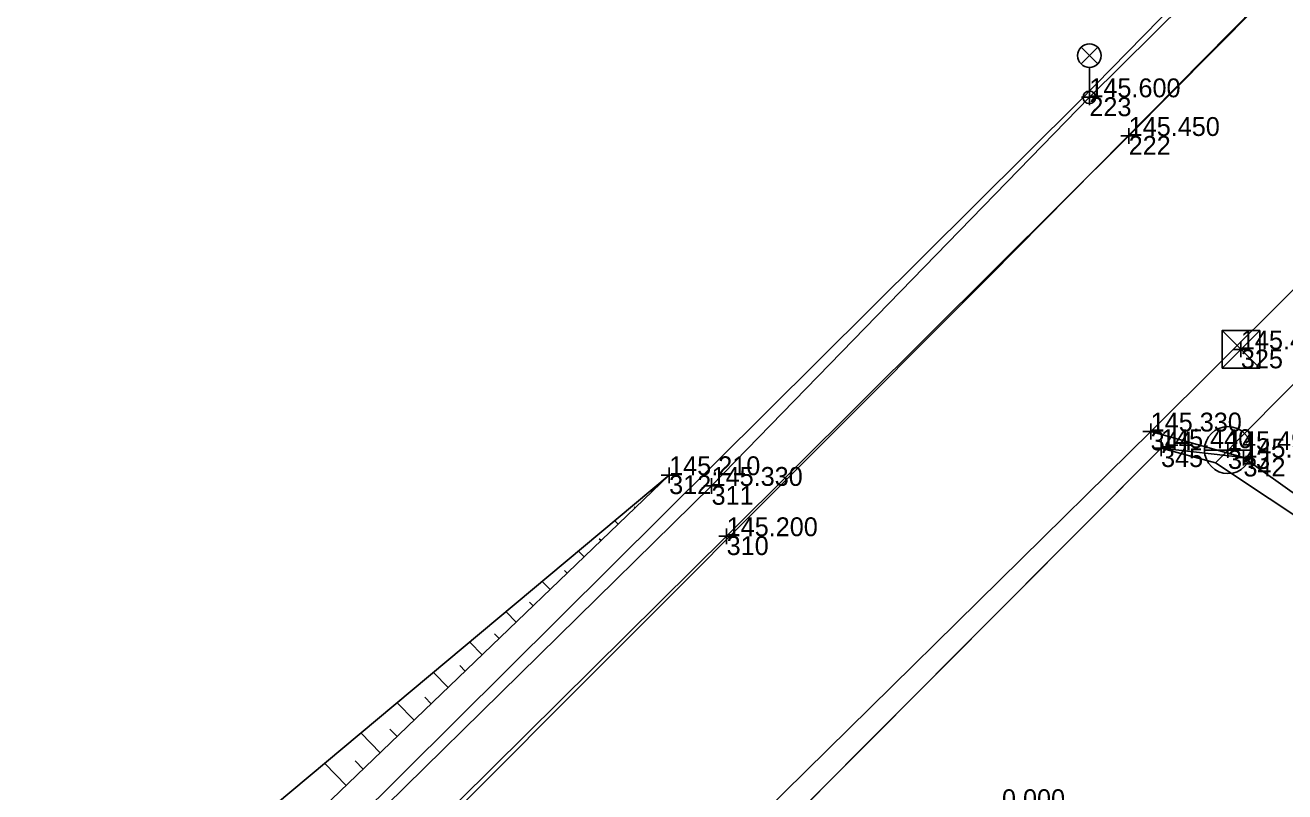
# Model space of a CAD drawing. Extents: x -748509 to -748117, y -967868 to -967533.
# Drawn here: x -748428.91 to -748388.83, y -967768.14 to -967743.76 of the extents above; entities that cross this region are included whole.
import ezdxf

# ---------------------------------------------------------------- set-up
doc = ezdxf.new("R2010")
doc.units = 0
for name, color, linetype in [('Body polohopisu', 7, 'Continuous'), ('Doplňkové značky', 7, 'Continuous'), ('KM', 7, 'Continuous'), ('Ploty_opěrné zdi', 7, 'Continuous'), ('Rozhraní ploch', 7, 'Continuous'), ('Výškopis', 7, 'Continuous'), ('Výšky bodů', 7, 'Continuous'), ('Značky IS', 7, 'Continuous'), ('Čísla bodů', 7, 'Continuous')]:
    doc.layers.add(name, color=color, linetype=linetype)

msp = doc.modelspace()

# ---------------------------------------------------------------- linework, layer by layer
at = {"layer": 'Body polohopisu'}
for p, q in [((-748395.05, -967746.05), (-748395.3, -967746.05)), ((-748395.05, -967746.05), (-748395.05, -967745.8)), ((-748395.05, -967746.05), (-748394.8, -967746.05)), ((-748395.05, -967746.05), (-748395.05, -967746.3)), ((-748393.8, -967747.28), (-748394.05, -967747.28)), ((-748393.8, -967747.28), (-748393.8, -967747.03)), ((-748393.8, -967747.28), (-748393.55, -967747.28)), ((-748393.8, -967747.28), (-748393.8, -967747.53)), ((-748390.23, -967754.07), (-748390.48, -967754.07)), ((-748390.23, -967754.07), (-748390.23, -967753.82)), ((-748390.23, -967754.07), (-748389.98, -967754.07)), ((-748390.23, -967754.07), (-748390.23, -967754.32)), ((-748393.1, -967756.68), (-748393.1, -967756.43)), ((-748393.1, -967756.68), (-748393.35, -967756.68)), ((-748393.1, -967756.68), (-748392.85, -967756.68)), ((-748393.1, -967756.68), (-748393.1, -967756.93)), ((-748392.77, -967757.21), (-748393.02, -967757.21)), ((-748392.77, -967757.21), (-748392.77, -967756.96)), ((-748392.77, -967757.21), (-748392.52, -967757.21)), ((-748392.77, -967757.21), (-748392.77, -967757.46)), ((-748390.64, -967757.27), (-748390.89, -967757.27)), ((-748390.64, -967757.27), (-748390.64, -967757.02)), ((-748390.64, -967757.27), (-748390.39, -967757.27)), ((-748390.64, -967757.27), (-748390.64, -967757.52)), ((-748390.15, -967757.51), (-748390.15, -967757.26)), ((-748390.15, -967757.51), (-748390.4, -967757.51)), ((-748390.15, -967757.51), (-748389.9, -967757.51)), ((-748390.15, -967757.51), (-748390.15, -967757.76)), ((-748408.42, -967758.07), (-748408.67, -967758.07)), ((-748408.42, -967758.07), (-748408.42, -967757.82)), ((-748408.42, -967758.07), (-748408.17, -967758.07)), ((-748408.42, -967758.07), (-748408.42, -967758.32)), ((-748407.07, -967758.41), (-748407.32, -967758.41)), ((-748407.07, -967758.41), (-748407.07, -967758.16)), ((-748407.07, -967758.41), (-748406.82, -967758.41)), ((-748407.07, -967758.41), (-748407.07, -967758.66)), ((-748406.59, -967760.01), (-748406.84, -967760.01)), ((-748406.59, -967760.01), (-748406.59, -967759.76)), ((-748406.59, -967760.01), (-748406.34, -967760.01)), ((-748406.59, -967760.01), (-748406.59, -967760.26))]:
    msp.add_line(p, q, dxfattribs=at)
at = {"layer": 'Doplňkové značky'}
for p, q in [((-748395.314, -967744.988), (-748394.786, -967744.46)), ((-748394.778, -967744.985), (-748395.306, -967744.456)), ((-748395.05, -967745.1), (-748395.05, -967745.85))]:
    msp.add_line(p, q, dxfattribs=at)
for centre, radius in [((-748395.05, -967744.725), 0.375), ((-748395.05, -967746.05), 0.2)]:
    msp.add_circle(centre, radius, dxfattribs=at)
at = {"layer": 'KM'}
msp.add_line((-748391.04, -967757.68), (-748387.38, -967753.98), dxfattribs=at)
for points in [[(-748245.234, -967554.317), (-748248, -967560.09), (-748251.25, -967566.35), (-748259.98, -967584.86), (-748268.35, -967600.05), (-748271.49, -967604.68), (-748279.6, -967616.66), (-748283.52, -967622.09), (-748309.26, -967655.94), (-748313.11, -967660.69), (-748315.81, -967663.73), (-748339.38, -967691.21), (-748366.68, -967719.8), (-748398.22, -967751.73), (-748421.72, -967775.27), (-748446.6, -967799.82), (-748468.93, -967821.53), (-748491.86, -967845.1), (-748500.525, -967854.438)], [(-748460.66, -967810.84), (-748447.72, -967798.11), (-748423.49, -967774.11), (-748395.38, -967746.18), (-748367.64, -967717.88), (-748340.8, -967689.65), (-748338.21, -967686.92)], [(-748409.975, -967774.486), (-748392.77, -967757.21), (-748391.04, -967757.68)], [(-748368.47, -967772.73), (-748379.15, -967765.58), (-748391.04, -967757.68)]]:
    msp.add_lwpolyline(points, dxfattribs=at)
at = {"layer": 'Ploty_opěrné zdi'}
msp.add_lwpolyline([(-748380.36, -967764.47), (-748390.15, -967757.51), (-748392.77, -967757.21), (-748412.07, -967776.59), (-748407.97, -967780.3)], dxfattribs=at)
at = {"layer": 'Rozhraní ploch'}
for points in [[(-748461.19, -967810.67), (-748460.51, -967811.08), (-748444.02, -967794.99), (-748439.01, -967789.86), (-748423.52, -967774.57), (-748407.07, -967758.41), (-748395.05, -967746.05), (-748380.78, -967731.92), (-748367.7, -967718.42), (-748351.79, -967701.78), (-748340.94, -967689.97), (-748337.38, -967685.41), (-748335.08, -967680.86), (-748328.55, -967672.15), (-748329.42, -967670.54)], [(-748339.41, -967690.9), (-748344.15, -967696.07), (-748355.97, -967708.43), (-748366.4, -967719.28), (-748377.52, -967730.86), (-748393.8, -967747.28), (-748406.59, -967760.01), (-748445.94, -967798.94), (-748468.02, -967820.71), (-748483.5, -967836.62)], [(-748393.1, -967756.68), (-748386.55, -967750.17)], [(-748390.15, -967757.51), (-748393.1, -967756.68), (-748412.31, -967775.59), (-748412.08, -967776.61)]]:
    msp.add_lwpolyline(points, dxfattribs=at)
at = {"layer": 'Výškopis'}
for points in [[(-748490.04, -967839.69), (-748471.35, -967820.54), (-748463.71, -967813.15), (-748465.99, -967810.06), (-748465.381, -967809.54), (-748464.62, -967808.89), (-748461.19, -967810.67), (-748446.48, -967795.95), (-748440.08, -967788.81), (-748425.07, -967774.06), (-748408.42, -967758.07)], [(-748408.42, -967758.07), (-748425.87, -967772.67), (-748441.27, -967786.47), (-748448.03, -967793.95), (-748457.02, -967803.73), (-748464.62, -967808.89), (-748465.99, -967810.06)], [(-748408.42, -967758.07), (-748408.42, -967758.07)], [(-748408.961, -967758.59), (-748408.997, -967758.552)], [(-748409.502, -967759.109), (-748409.53, -967759.079)], [(-748410.043, -967759.629), (-748410.15, -967759.517)], [(-748410.584, -967760.148), (-748410.641, -967760.089)], [(-748411.125, -967760.668), (-748411.303, -967760.482)], [(-748411.666, -967761.187), (-748411.751, -967761.098)], [(-748412.207, -967761.707), (-748412.456, -967761.447)], [(-748412.748, -967762.226), (-748412.862, -967762.107)], [(-748413.288, -967762.746), (-748413.609, -967762.412)], [(-748413.829, -967763.265), (-748413.972, -967763.117)], [(-748414.37, -967763.785), (-748414.762, -967763.376)], [(-748414.911, -967764.304), (-748415.082, -967764.126)], [(-748415.452, -967764.824), (-748415.915, -967764.341)], [(-748416.534, -967765.863), (-748417.069, -967765.306)], [(-748415.993, -967765.343), (-748416.193, -967765.135)], [(-748417.075, -967766.382), (-748417.303, -967766.145)], [(-748417.616, -967766.902), (-748418.222, -967766.271)], [(-748418.698, -967767.941), (-748419.375, -967767.236)], [(-748418.157, -967767.421), (-748418.413, -967767.154)]]:
    msp.add_lwpolyline(points, dxfattribs=at)
at = {"layer": 'Značky IS'}
for p, q in [((-748390.83, -967753.47), (-748389.63, -967754.67)), ((-748389.63, -967753.47), (-748390.83, -967754.67)), ((-748389.892, -967757.27), (-748391.388, -967757.27))]:
    msp.add_line(p, q, dxfattribs=at)
msp.add_lwpolyline([(-748390.83, -967754.67), (-748389.63, -967754.67), (-748389.63, -967753.47), (-748390.83, -967753.47)], close=True, dxfattribs=at)
for start, end in [(0, 180), (180, 0)]:
    msp.add_arc((-748390.64, -967757.27), 0.747, start, end, dxfattribs=at)

# ---------------------------------------------------------------- texts
at = {"layer": 'Výšky bodů'}
for s, p in [('145.600', (-748395.05, -967746.05)), ('145.450', (-748393.8, -967747.28)), ('145.400', (-748390.23, -967754.07)), ('145.330', (-748393.1, -967756.68)), ('145.440', (-748392.77, -967757.21)), ('145.490', (-748390.64, -967757.27)), ('145.480', (-748390.15, -967757.51)), ('145.210', (-748408.42, -967758.07)), ('145.330', (-748407.07, -967758.41)), ('145.200', (-748406.59, -967760.01)), ('0.000', (-748397.83, -967768.66))]:
    msp.add_text(s, height=0.6, dxfattribs=at).set_placement(p)
at = {"layer": 'Čísla bodů'}
for s, p in [('223', (-748395.05, -967746.65)), ('222', (-748393.8, -967747.88)), ('325', (-748390.23, -967754.67)), ('344', (-748393.1, -967757.28)), ('345', (-748392.77, -967757.81)), ('343', (-748390.64, -967757.87)), ('342', (-748390.15, -967758.11)), ('312', (-748408.42, -967758.67)), ('311', (-748407.07, -967759.01)), ('310', (-748406.59, -967760.61))]:
    msp.add_text(s, height=0.6, dxfattribs=at).set_placement(p)

doc.saveas('drawing.dxf')
